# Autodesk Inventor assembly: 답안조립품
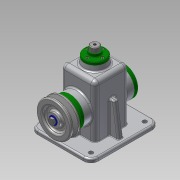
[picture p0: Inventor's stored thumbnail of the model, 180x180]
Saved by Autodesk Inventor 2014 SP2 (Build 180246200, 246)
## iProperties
Created: 2016-08
Part Number: 답안조립품
Document SubType Name: Assembly
Designer: user
Author: user
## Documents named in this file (19)
- C:\Users\user\Desktop\460820V1003\답안조립품.iam
- C:\Users\user\Desktop\460820V1003\본체.ipt
- C:\Users\user\Desktop\460820V1003\V-벨트풀리.ipt
- C:\Users\user\Desktop\460820V1003\고정핀.ipt
- C:\Users\user\Desktop\460820V1003\뒤커버.ipt
- C:\Users\user\Desktop\460820V1003\링크.ipt
- C:\Users\user\Desktop\460820V1003\멈춤링 6 x 5.ipt
- C:\Users\user\Desktop\460820V1003\멈춤링 15 x 1.ipt
- C:\Users\user\Desktop\460820V1003\베어링 15 x 35 x 11.ipt
- C:\Users\user\Desktop\460820V1003\볼트 M3 x 8.ipt
- C:\Users\user\Desktop\460820V1003\볼트 M4 x 10.ipt
- C:\Users\user\Desktop\460820V1003\볼트 M6 x 12.ipt
- C:\Users\user\Desktop\460820V1003\상부부시.ipt
- C:\Users\user\Desktop\460820V1003\슬라이드바.ipt
- C:\Users\user\Desktop\460820V1003\앞커버.ipt
- C:\Users\user\Desktop\460820V1003\오일실 15 25 7.ipt
- C:\Users\user\Desktop\460820V1003\와셔.ipt
- C:\Users\user\Desktop\460820V1003\키 5 x 5 x 14.ipt
- C:\Users\user\Desktop\460820V1003\편심축.ipt
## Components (15 placed, 5 different names)
1. V-벨트풀리:1 — 각도:1
2. 고정핀:1 — 각도:5
3. ISO 4018 M6 x 12:1 — 강체:2, 구동, 각도:6
4. ISO 4762 M4 x 10:2 — 강체:3
5. ISO 4762 M4 x 10:1 — 강체:4
6. ISO 4762 M4 x 10:3
7. ISO 4762 M4 x 10:4
8. ISO 4762 M4 x 10:5
9. ISO 4762 M4 x 10:6
10. ISO 4762 M4 x 10:7
11. ISO 4762 M4 x 10:8
12. ISO 4762 M3 x 8:1 — 강체:5
13. ISO 4762 M3 x 8:2
14. ISO 4762 M3 x 8:3
15. ISO 4762 M3 x 8:4
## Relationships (8: Angle 4, WeldJoint 4)
- 각도:1 [Angle]: V-벨트풀리:1
- 강체:2 [WeldJoint]: ISO 4018 M6 x 12:1
- 강체:3 [WeldJoint]: ISO 4762 M4 x 10:2
- 강체:4 [WeldJoint]: ISO 4762 M4 x 10:1
- 강체:5 [WeldJoint]: ISO 4762 M3 x 8:1
- 구동 [Angle]: ISO 4018 M6 x 12:1
- 각도:5 [Angle]: 고정핀:1
- 각도:6 [Angle]: ISO 4018 M6 x 12:1
